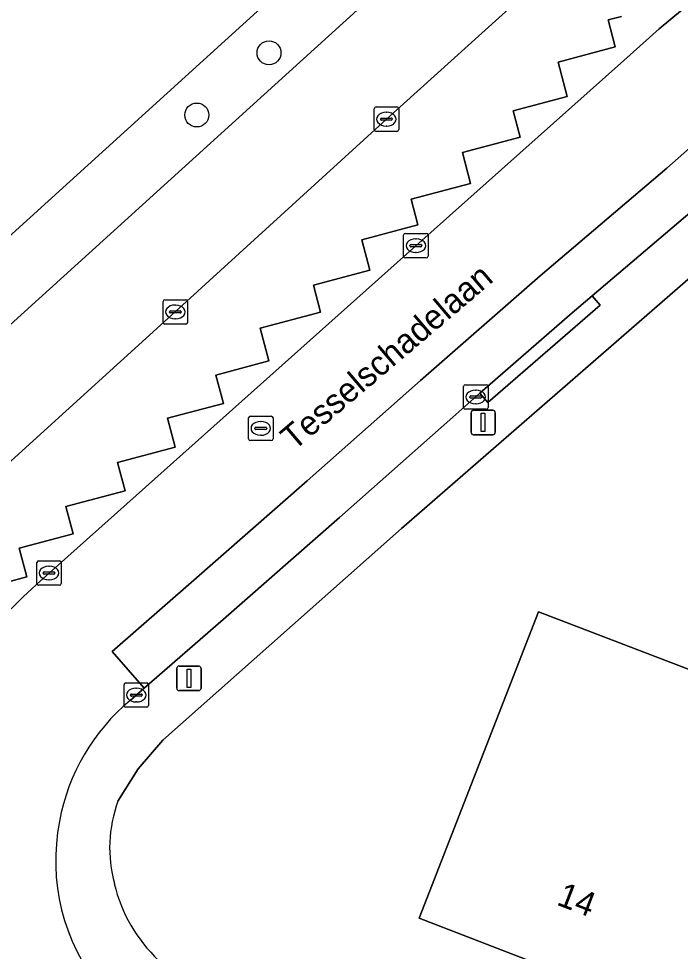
# Model space of a CAD drawing. Extents: x 161347 to 161881, y 382161 to 382804.
# Drawn here: x 161665.47 to 161692.52, y 382514.18 to 382552.31 of the extents above; entities that cross this region are included whole.
import ezdxf

# ---------------------------------------------------------------- set-up
doc = ezdxf.new("R2010")
doc.units = 0
for name, color, linetype in [('IMGEO_Boom', 7, 'Continuous'), ('IMGEO_Erf', 7, 'Continuous'), ('IMGEO_Groenvoorziening', 7, 'Continuous'), ('IMGEO_Haag', 7, 'Continuous'), ('IMGEO_Kolk', 7, 'Continuous'), ('IMGEO_Lichtmast', 7, 'Continuous'), ('IMGEO_Openbare_ruimte_label', 7, 'Continuous'), ('IMGEO_Pand', 7, 'Continuous'), ('IMGEO_Pand_nummerreeks', 7, 'Continuous'), ('IMGEO_Parkeervlak_gesloten', 7, 'Continuous'), ('IMGEO_Parkeervlak_open', 7, 'Continuous'), ('IMGEO_Rijbaan_lokaal_gesloten', 7, 'Continuous'), ('IMGEO_Rijbaan_lokaal_open', 7, 'Continuous'), ('IMGEO_Rioolput', 7, 'Continuous'), ('IMGEO_Voetpad_open', 7, 'Continuous')]:
    doc.layers.add(name, color=color, linetype=linetype)

msp = doc.modelspace()

# ---------------------------------------------------------------- linework, layer by layer
at = {"layer": 'IMGEO_Boom'}
for centre in [(161675.705, 382550.908), (161672.751, 382548.367)]:
    msp.add_circle(centre, 0.489, dxfattribs=at)
at = {"layer": 'IMGEO_Erf'}
for points in [[(161794.971, 382530.118), (161792.241, 382536.131), (161792.378, 382536.972), (161792.323, 382537.821), (161791.654, 382539.638), (161791.061, 382540.405), (161790.328, 382541.011), (161790.189, 382541.423), (161789.107, 382540.979), (161788.094, 382543.265), (161787.424, 382542.968), (161782.001, 382556.605), (161781.188, 382558.978), (161780.231, 382559.421), (161779.298, 382559.715), (161776.187, 382560.249), (161770.93, 382560.454), (161716.681, 382562.374), (161709.058, 382555.75), (161702.444, 382550.002), (161681.121, 382531.471), (161671.366, 382522.817), (161670.351, 382521.638), (161669.529, 382520.317)], [(161686.999, 382513.547), (161681.847, 382515.536), (161686.722, 382528.062), (161695.912, 382524.537), (161697.513, 382528.711), (161701.108, 382527.333), (161701.274, 382527.709), (161701.407, 382528.011), (161702.78, 382531.122), (161702.913, 382531.424), (161704.863, 382535.846), (161705.209, 382536.63), (161718.281, 382530.16), (161711.723, 382517.008), (161713.495, 382516.124), (161710.939, 382510.999)]]:
    msp.add_lwpolyline(points, dxfattribs=at)
for centre, radius, start, end in [((161674.782, 382518.398), 5.592, 159.9358, 195.0334), ((161675.503, 382518.391), 6.29, 193.2644, 226.7315)]:
    msp.add_arc(centre, radius, start, end, dxfattribs=at)
at = {"layer": 'IMGEO_Groenvoorziening'}
msp.add_lwpolyline([(161676.253, 382553.55), (161643.672, 382523.978), (161645.836, 382522.287), (161652.099, 382527.995), (161684.128, 382557.046), (161682.265, 382559.016)], close=True, dxfattribs=at)
for points in [[(161681.712, 382543.025), (161690.206, 382550.598), (161691.651, 382551.884), (161694.524, 382554.274)], [(161690.119, 382552.398), (161689.571, 382552.252), (161689.864, 382551.148), (161687.527, 382550.526), (161687.9, 382549.123), (161685.689, 382548.535), (161685.975, 382547.461), (161683.612, 382546.833), (161683.948, 382545.572), (161681.511, 382544.924), (161681.789, 382543.88), (161679.495, 382543.27), (161679.825, 382542.031), (161677.519, 382541.417), (161677.813, 382540.311), (161675.339, 382539.653), (161675.696, 382538.314), (161673.531, 382537.738), (161673.839, 382536.58), (161671.551, 382535.971), (161671.864, 382534.794), (161669.509, 382534.167), (161669.818, 382533.006), (161667.397, 382532.361), (161667.694, 382531.243), (161665.493, 382530.658), (161665.805, 382529.486), (161663.371, 382528.839)], [(161666.712, 382529.643), (161681.712, 382543.025)]]:
    msp.add_lwpolyline(points, dxfattribs=at)
msp.add_arc((161694.552, 382498.45), 41.81, 131.7494, 152.492, dxfattribs=at)
at = {"layer": 'IMGEO_Haag'}
msp.add_lwpolyline([(161676.253, 382553.55), (161643.672, 382523.978), (161645.836, 382522.287), (161652.099, 382527.995), (161684.128, 382557.046), (161682.265, 382559.016)], close=True, dxfattribs=at)
at = {"layer": 'IMGEO_Kolk'}
for p, q in [((161680.006, 382547.771), (161680.006, 382548.623)), ((161680.081, 382548.697), (161680.933, 382548.697)), ((161681.007, 382548.623), (161681.007, 382547.771)), ((161680.308, 382548.24), (161680.706, 382548.24)), ((161680.494, 382548.477), (161680.519, 382548.477)), ((161680.265, 382548.191), (161680.265, 382548.203)), ((161680.703, 382548.154), (161680.305, 382548.154)), ((161680.517, 382547.917), (161680.492, 382547.917)), ((161680.749, 382548.203), (161680.749, 382548.191)), ((161680.933, 382547.697), (161680.081, 382547.697)), ((161681.21, 382542.6), (161681.21, 382543.452)), ((161681.285, 382543.526), (161682.137, 382543.526)), ((161681.698, 382543.306), (161681.723, 382543.306)), ((161682.211, 382543.452), (161682.211, 382542.6)), ((161681.469, 382543.02), (161681.469, 382543.032)), ((161681.907, 382542.983), (161681.509, 382542.983)), ((161681.512, 382543.069), (161681.91, 382543.069)), ((161681.953, 382543.032), (161681.953, 382543.02)), ((161682.137, 382542.526), (161681.285, 382542.526)), ((161681.721, 382542.746), (161681.696, 382542.746)), ((161671.374, 382539.891), (161671.374, 382540.743)), ((161671.449, 382540.817), (161672.301, 382540.817)), ((161671.862, 382540.597), (161671.887, 382540.597)), ((161672.375, 382540.743), (161672.375, 382539.891)), ((161671.633, 382540.311), (161671.633, 382540.323)), ((161672.071, 382540.274), (161671.673, 382540.274)), ((161671.676, 382540.36), (161672.074, 382540.36)), ((161672.117, 382540.323), (161672.117, 382540.311)), ((161671.885, 382540.037), (161671.86, 382540.037)), ((161672.301, 382539.817), (161671.449, 382539.817)), ((161683.658, 382536.415), (161683.658, 382537.267)), ((161683.733, 382537.341), (161684.585, 382537.341)), ((161684.659, 382537.267), (161684.659, 382536.415)), ((161683.917, 382536.835), (161683.917, 382536.847)), ((161684.355, 382536.798), (161683.957, 382536.798)), ((161683.96, 382536.884), (161684.358, 382536.884)), ((161684.146, 382537.121), (161684.171, 382537.121)), ((161684.401, 382536.847), (161684.401, 382536.835)), ((161684.169, 382536.561), (161684.144, 382536.561)), ((161684.585, 382536.341), (161683.733, 382536.341)), ((161666.211, 382529.218), (161666.211, 382530.07)), ((161666.286, 382530.144), (161667.138, 382530.144)), ((161666.699, 382529.924), (161666.724, 382529.924)), ((161667.212, 382530.07), (161667.212, 382529.218)), ((161666.47, 382529.638), (161666.47, 382529.65)), ((161666.908, 382529.601), (161666.51, 382529.601)), ((161666.513, 382529.687), (161666.911, 382529.687)), ((161666.954, 382529.65), (161666.954, 382529.638)), ((161666.722, 382529.364), (161666.697, 382529.364)), ((161667.138, 382529.144), (161666.286, 382529.144)), ((161669.778, 382524.229), (161669.778, 382525.081)), ((161669.853, 382525.155), (161670.705, 382525.155)), ((161670.779, 382525.081), (161670.779, 382524.229)), ((161670.037, 382524.649), (161670.037, 382524.661)), ((161670.475, 382524.612), (161670.077, 382524.612)), ((161670.08, 382524.698), (161670.478, 382524.698)), ((161670.266, 382524.935), (161670.291, 382524.935)), ((161670.521, 382524.661), (161670.521, 382524.649)), ((161670.289, 382524.375), (161670.264, 382524.375)), ((161670.705, 382524.155), (161669.853, 382524.155))]:
    msp.add_line(p, q, dxfattribs=at)
for points in [[(161680.006, 382547.771), (161680.006, 382548.623)], [(161680.081, 382548.697), (161680.933, 382548.697)], [(161681.007, 382548.623), (161681.007, 382547.771)], [(161680.933, 382547.697), (161680.081, 382547.697)], [(161681.21, 382542.6), (161681.21, 382543.452)], [(161681.285, 382543.526), (161682.137, 382543.526)], [(161682.211, 382543.452), (161682.211, 382542.6)], [(161682.137, 382542.526), (161681.285, 382542.526)], [(161671.374, 382539.891), (161671.374, 382540.743)], [(161671.449, 382540.817), (161672.301, 382540.817)], [(161672.375, 382540.743), (161672.375, 382539.891)], [(161672.301, 382539.817), (161671.449, 382539.817)], [(161683.658, 382536.415), (161683.658, 382537.267)], [(161683.733, 382537.341), (161684.585, 382537.341)], [(161684.659, 382537.267), (161684.659, 382536.415)], [(161684.585, 382536.341), (161683.733, 382536.341)], [(161666.211, 382529.218), (161666.211, 382530.07)], [(161666.286, 382530.144), (161667.138, 382530.144)], [(161667.212, 382530.07), (161667.212, 382529.218)], [(161667.138, 382529.144), (161666.286, 382529.144)], [(161669.778, 382524.229), (161669.778, 382525.081)], [(161669.853, 382525.155), (161670.705, 382525.155)], [(161670.779, 382525.081), (161670.779, 382524.229)], [(161670.705, 382524.155), (161669.853, 382524.155)]]:
    msp.add_lwpolyline(points, dxfattribs=at)
for centre, radius, start, end in [((161680.083, 382548.621), 0.0765, 91.552, 178.448), ((161680.083, 382548.621), 0.0765, 91.552, 178.448), ((161680.931, 382548.621), 0.0765, 1.552, 88.448), ((161680.931, 382548.621), 0.0765, 1.552, 88.448), ((161680.305, 382548.2), 0.0403, 85.8775, 175.7526), ((161680.71, 382548.202), 0.0386, 1.7309, 96.639), ((161680.302, 382548.19), 0.0366, 178.938, 274.7102), ((161680.706, 382548.197), 0.043, 264.8664, 352.4533), ((161680.083, 382547.773), 0.0765, 181.552, 268.448), ((161680.083, 382547.773), 0.0765, 181.552, 268.448), ((161680.931, 382547.773), 0.0765, 271.552, 358.448), ((161680.931, 382547.773), 0.0765, 271.552, 358.448), ((161681.287, 382543.45), 0.0765, 91.552, 178.448), ((161681.287, 382543.45), 0.0765, 91.552, 178.448), ((161682.135, 382543.45), 0.0765, 1.552, 88.448), ((161682.135, 382543.45), 0.0765, 1.552, 88.448), ((161681.509, 382543.029), 0.0403, 85.8775, 175.7526), ((161681.506, 382543.019), 0.0366, 178.938, 274.7102), ((161681.91, 382543.026), 0.043, 264.8664, 352.4533), ((161681.914, 382543.031), 0.0386, 1.7309, 96.639), ((161681.287, 382542.602), 0.0765, 181.552, 268.448), ((161681.287, 382542.602), 0.0765, 181.552, 268.448), ((161682.135, 382542.602), 0.0765, 271.552, 358.448), ((161682.135, 382542.602), 0.0765, 271.552, 358.448), ((161671.451, 382540.741), 0.0765, 91.552, 178.448), ((161671.451, 382540.741), 0.0765, 91.552, 178.448), ((161672.299, 382540.741), 0.0765, 1.552, 88.448), ((161672.299, 382540.741), 0.0765, 1.552, 88.448), ((161671.673, 382540.32), 0.0403, 85.8775, 175.7526), ((161671.67, 382540.31), 0.0366, 178.938, 274.7102), ((161672.074, 382540.317), 0.043, 264.8664, 352.4533), ((161672.078, 382540.322), 0.0386, 1.7309, 96.639), ((161671.451, 382539.893), 0.0765, 181.552, 268.448), ((161671.451, 382539.893), 0.0765, 181.552, 268.448), ((161672.299, 382539.893), 0.0765, 271.552, 358.448), ((161672.299, 382539.893), 0.0765, 271.552, 358.448), ((161683.735, 382537.265), 0.0765, 91.552, 178.448), ((161683.735, 382537.265), 0.0765, 91.552, 178.448), ((161684.583, 382537.265), 0.0765, 1.552, 88.448), ((161684.583, 382537.265), 0.0765, 1.552, 88.448), ((161683.957, 382536.844), 0.0403, 85.8775, 175.7526), ((161683.954, 382536.834), 0.0366, 178.938, 274.7102), ((161684.358, 382536.841), 0.043, 264.8664, 352.4533), ((161684.362, 382536.846), 0.0386, 1.7309, 96.639), ((161683.735, 382536.417), 0.0765, 181.552, 268.448), ((161683.735, 382536.417), 0.0765, 181.552, 268.448), ((161684.583, 382536.417), 0.0765, 271.552, 358.448), ((161684.583, 382536.417), 0.0765, 271.552, 358.448), ((161666.288, 382530.068), 0.0765, 91.552, 178.448), ((161666.288, 382530.068), 0.0765, 91.552, 178.448), ((161667.136, 382530.068), 0.0765, 1.552, 88.448), ((161667.136, 382530.068), 0.0765, 1.552, 88.448), ((161666.51, 382529.647), 0.0403, 85.8775, 175.7526), ((161666.507, 382529.637), 0.0366, 178.938, 274.7102), ((161666.911, 382529.644), 0.043, 264.8664, 352.4533), ((161666.915, 382529.649), 0.0386, 1.7309, 96.639), ((161666.288, 382529.22), 0.0765, 181.552, 268.448), ((161666.288, 382529.22), 0.0765, 181.552, 268.448), ((161667.136, 382529.22), 0.0765, 271.552, 358.448), ((161667.136, 382529.22), 0.0765, 271.552, 358.448), ((161669.855, 382525.079), 0.0765, 91.552, 178.448), ((161669.855, 382525.079), 0.0765, 91.552, 178.448), ((161670.703, 382525.079), 0.0765, 1.552, 88.448), ((161670.703, 382525.079), 0.0765, 1.552, 88.448), ((161670.077, 382524.658), 0.0403, 85.8775, 175.7526), ((161670.074, 382524.648), 0.0366, 178.938, 274.7102), ((161670.478, 382524.655), 0.043, 264.8664, 352.4533), ((161670.482, 382524.66), 0.0386, 1.7309, 96.639), ((161669.855, 382524.231), 0.0765, 181.552, 268.448), ((161669.855, 382524.231), 0.0765, 181.552, 268.448), ((161670.703, 382524.231), 0.0765, 271.552, 358.448), ((161670.703, 382524.231), 0.0765, 271.552, 358.448)]:
    msp.add_arc(centre, radius, start, end, dxfattribs=at)
for centre, major_axis, ratio, start_param, end_param in [((161680.493, 382548.197), (-0.387, 0.002), 0.722429, 4.712389, 7.853982), ((161680.518, 382548.197), (-0.39, 0.002), 0.717154, 1.570796, 4.712389), ((161681.697, 382543.026), (-0.387, 0.002), 0.722429, 4.712389, 7.853982), ((161681.722, 382543.026), (-0.39, 0.002), 0.717154, 1.570796, 4.712389), ((161671.861, 382540.317), (-0.387, 0.002), 0.722429, 4.712389, 7.853982), ((161671.886, 382540.317), (-0.39, 0.002), 0.717154, 1.570796, 4.712389), ((161684.145, 382536.841), (-0.387, 0.002), 0.722429, 4.712389, 7.853982), ((161684.17, 382536.841), (-0.39, 0.002), 0.717154, 1.570796, 4.712389), ((161666.698, 382529.644), (-0.387, 0.002), 0.722429, 4.712389, 7.853982), ((161666.723, 382529.644), (-0.39, 0.002), 0.717154, 1.570796, 4.712389), ((161670.265, 382524.655), (-0.387, 0.002), 0.722429, 4.712389, 7.853982), ((161670.29, 382524.655), (-0.39, 0.002), 0.717154, 1.570796, 4.712389)]:
    msp.add_ellipse(centre, major_axis=major_axis, ratio=ratio, start_param=start_param, end_param=end_param, dxfattribs=at)
at = {"layer": 'IMGEO_Lichtmast'}
for p, q in [((161683.966, 382535.398), (161683.966, 382536.198)), ((161683.966, 382536.198), (161683.966, 382535.398)), ((161684.066, 382536.298), (161684.856, 382536.298)), ((161684.856, 382536.298), (161684.066, 382536.298)), ((161684.956, 382536.198), (161684.956, 382535.398)), ((161684.956, 382535.398), (161684.956, 382536.198)), ((161684.856, 382535.298), (161684.066, 382535.298)), ((161684.066, 382535.298), (161684.856, 382535.298)), ((161671.935, 382524.938), (161671.935, 382525.738)), ((161671.935, 382525.738), (161671.935, 382524.938)), ((161672.035, 382525.838), (161672.825, 382525.838)), ((161672.825, 382525.838), (161672.035, 382525.838)), ((161672.925, 382525.738), (161672.925, 382524.938)), ((161672.925, 382524.938), (161672.925, 382525.738)), ((161672.825, 382524.838), (161672.035, 382524.838)), ((161672.035, 382524.838), (161672.825, 382524.838))]:
    msp.add_line(p, q, dxfattribs=at)
for points in [[(161684.386, 382536.173), (161684.536, 382536.173), (161684.536, 382535.423), (161684.386, 382535.423), (161684.386, 382536.173)], [(161672.355, 382525.713), (161672.505, 382525.713), (161672.505, 382524.963), (161672.355, 382524.963), (161672.355, 382525.713)]]:
    msp.add_lwpolyline(points, dxfattribs=at)
for centre, start, end in [((161684.066, 382536.198), 90, 180), ((161684.066, 382536.198), 90, 180), ((161684.856, 382536.198), 0, 90), ((161684.856, 382536.198), 360, 90), ((161684.066, 382535.398), 180, 270), ((161684.066, 382535.398), 180, 270), ((161684.856, 382535.398), 270, 0), ((161684.856, 382535.398), 270, 0), ((161672.035, 382525.738), 90, 180), ((161672.035, 382525.738), 90, 180), ((161672.825, 382525.738), 0, 90), ((161672.825, 382525.738), 360, 90), ((161672.035, 382524.938), 180, 270), ((161672.035, 382524.938), 180, 270), ((161672.825, 382524.938), 270, 0), ((161672.825, 382524.938), 270, 0)]:
    msp.add_arc(centre, 0.1, start, end, dxfattribs=at)
at = {"layer": 'IMGEO_Pand'}
for points in [[(161684.928, 382563.407), (161678.388, 382570.921), (161674.636, 382567.532), (161638.938, 382535.131), (161638.008, 382536.155), (161634.759, 382533.207), (161640.057, 382527.369), (161643.393, 382523.725), (161643.672, 382523.978), (161676.253, 382553.55), (161682.265, 382559.016), (161681.273, 382560.072), (161682.89, 382561.547)], [(161701.067, 382516.209), (161701.422, 382516.032), (161705.884, 382524.94), (161701.108, 382527.333), (161697.513, 382528.711), (161695.912, 382524.537), (161686.722, 382528.062), (161681.847, 382515.536), (161686.999, 382513.547), (161686.863, 382513.2), (161690.987, 382511.583), (161691.144, 382511.985), (161692.567, 382511.427), (161696.188, 382520.662), (161699.202, 382519.424), (161698.274, 382517.607), (161698.645, 382517.421)]]:
    msp.add_lwpolyline(points, close=True, dxfattribs=at)
at = {"layer": 'IMGEO_Parkeervlak_gesloten'}
msp.add_lwpolyline([(161670.597, 382524.931), (161673.831, 382527.746), (161678.594, 382531.918), (161683.217, 382536.02), (161684.328, 382536.99), (161688.1, 382540.282), (161688.915, 382540.975), (161693.273, 382544.684), (161697.808, 382548.669), (161696.498, 382550.18), (161691.965, 382546.197), (161686.794, 382541.797), (161681.896, 382537.521), (161677.271, 382533.418), (161672.516, 382529.253), (161669.286, 382526.443)], close=True, dxfattribs=at)
at = {"layer": 'IMGEO_Parkeervlak_open'}
for points in [[(161692.48, 382559.009), (161680.506, 382548.198), (161671.874, 382540.317), (161662.915, 382532.2)], [(161663.371, 382528.839), (161665.805, 382529.486), (161665.493, 382530.658), (161667.694, 382531.243), (161667.397, 382532.361), (161669.818, 382533.006), (161669.509, 382534.167), (161671.864, 382534.794), (161671.551, 382535.971), (161673.839, 382536.58), (161673.531, 382537.738), (161675.696, 382538.314), (161675.339, 382539.653), (161677.813, 382540.311), (161677.519, 382541.417), (161679.825, 382542.031), (161679.495, 382543.27), (161681.789, 382543.88), (161681.511, 382544.924), (161683.948, 382545.572), (161683.612, 382546.833), (161685.975, 382547.461), (161685.689, 382548.535), (161687.9, 382549.123), (161687.527, 382550.526), (161689.864, 382551.148), (161689.571, 382552.252), (161690.119, 382552.398)]]:
    msp.add_lwpolyline(points, dxfattribs=at)
at = {"layer": 'IMGEO_Rijbaan_lokaal_gesloten'}
for points in [[(161705.768, 382563.927), (161700.093, 382558.908), (161694.524, 382554.274), (161691.651, 382551.884), (161690.206, 382550.598), (161681.712, 382543.025), (161666.712, 382529.643)], [(161670.026, 382524.435), (161670.597, 382524.931), (161669.286, 382526.443), (161672.516, 382529.253), (161677.271, 382533.418), (161681.896, 382537.521), (161686.794, 382541.797), (161691.965, 382546.197), (161696.498, 382550.18), (161697.808, 382548.669), (161698.795, 382549.536), (161701.128, 382551.574), (161703.639, 382553.768), (161707.699, 382557.212)]]:
    msp.add_lwpolyline(points, dxfattribs=at)
for centre, radius, start, end in [((161694.552, 382498.45), 41.81, 131.7494, 152.492), ((161675.414, 382517.973), 8.414, 129.8184, 169.6097), ((161675.236, 382517.879), 8.256, 168.7465, 219.2945)]:
    msp.add_arc(centre, radius, start, end, dxfattribs=at)
at = {"layer": 'IMGEO_Rijbaan_lokaal_open'}
msp.add_lwpolyline([(161680.506, 382548.198), (161692.48, 382559.009), (161689.676, 382562.09), (161688.624, 382561.141), (161687.482, 382560.098), (161685.729, 382558.534), (161684.649, 382559.706), (161683.982, 382560.43), (161687.944, 382564.02), (161687.648, 382564.351), (161683.638, 382560.672), (161682.89, 382561.547), (161681.273, 382560.072), (161682.265, 382559.016), (161684.128, 382557.046), (161652.099, 382527.995), (161653.308, 382523.528), (161654.315, 382524.377), (161662.915, 382532.2), (161671.874, 382540.317)], close=True, dxfattribs=at)
at = {"layer": 'IMGEO_Rioolput'}
for p, q in [((161674.944, 382536.057), (161675.796, 382536.057)), ((161674.869, 382535.131), (161674.869, 382535.983)), ((161675.357, 382535.837), (161675.382, 382535.837)), ((161675.87, 382535.983), (161675.87, 382535.131)), ((161675.128, 382535.551), (161675.128, 382535.563)), ((161675.566, 382535.514), (161675.168, 382535.514)), ((161675.171, 382535.6), (161675.569, 382535.6)), ((161675.38, 382535.277), (161675.355, 382535.277)), ((161675.612, 382535.563), (161675.612, 382535.551)), ((161675.796, 382535.057), (161674.944, 382535.057))]:
    msp.add_line(p, q, dxfattribs=at)
for points in [[(161674.944, 382536.057), (161675.796, 382536.057)], [(161674.869, 382535.131), (161674.869, 382535.983)], [(161675.87, 382535.983), (161675.87, 382535.131)], [(161675.796, 382535.057), (161674.944, 382535.057)]]:
    msp.add_lwpolyline(points, dxfattribs=at)
for centre, radius, start, end in [((161674.946, 382535.981), 0.0765, 91.552, 178.448), ((161674.946, 382535.981), 0.0765, 91.552, 178.448), ((161675.794, 382535.981), 0.0765, 1.552, 88.448), ((161675.794, 382535.981), 0.0765, 1.552, 88.448), ((161675.168, 382535.56), 0.0403, 85.8775, 175.7526), ((161675.165, 382535.55), 0.0366, 178.938, 274.7102), ((161675.569, 382535.557), 0.043, 264.8664, 352.4533), ((161675.573, 382535.562), 0.0386, 1.7309, 96.639), ((161674.946, 382535.133), 0.0765, 181.552, 268.448), ((161674.946, 382535.133), 0.0765, 181.552, 268.448), ((161675.794, 382535.133), 0.0765, 271.552, 358.448), ((161675.794, 382535.133), 0.0765, 271.552, 358.448)]:
    msp.add_arc(centre, radius, start, end, dxfattribs=at)
for centre, major_axis, ratio, start_param, end_param in [((161675.356, 382535.557), (-0.387, 0.002), 0.722429, 4.712389, 7.853982), ((161675.381, 382535.557), (-0.39, 0.002), 0.717154, 1.570796, 4.712389)]:
    msp.add_ellipse(centre, major_axis=major_axis, ratio=ratio, start_param=start_param, end_param=end_param, dxfattribs=at)
at = {"layer": 'IMGEO_Voetpad_open'}
for points in [[(161681.121, 382531.471), (161702.444, 382550.002), (161701.128, 382551.574), (161698.795, 382549.536), (161697.808, 382548.669), (161693.273, 382544.684), (161688.915, 382540.975), (161689.242, 382540.598), (161684.655, 382536.613), (161684.328, 382536.99), (161683.217, 382536.02), (161678.594, 382531.918), (161673.831, 382527.746), (161670.597, 382524.931), (161670.026, 382524.435)], [(161669.529, 382520.317), (161670.351, 382521.638), (161671.366, 382522.817), (161681.121, 382531.471)]]:
    msp.add_lwpolyline(points, dxfattribs=at)
msp.add_lwpolyline([(161684.328, 382536.99), (161684.655, 382536.613), (161689.242, 382540.598), (161688.915, 382540.975), (161688.1, 382540.282)], close=True, dxfattribs=at)
for centre, radius, start, end in [((161675.414, 382517.973), 8.414, 129.8184, 169.6097), ((161674.782, 382518.398), 5.592, 159.9358, 195.0334), ((161675.236, 382517.879), 8.256, 168.7465, 219.2945), ((161675.503, 382518.391), 6.29, 193.2644, 226.7315)]:
    msp.add_arc(centre, radius, start, end, dxfattribs=at)

# ---------------------------------------------------------------- texts
at = {"layer": 'IMGEO_Openbare_ruimte_label'}
msp.add_text('Tesselschadelaan', height=1, rotation=40.3776, dxfattribs=at).set_placement((161676.722, 382534.614))
at = {"layer": 'IMGEO_Pand_nummerreeks'}
msp.add_text('14', height=1, rotation=339.0281, dxfattribs=at).set_placement((161687.423, 382516.098))

doc.saveas('drawing.dxf')
